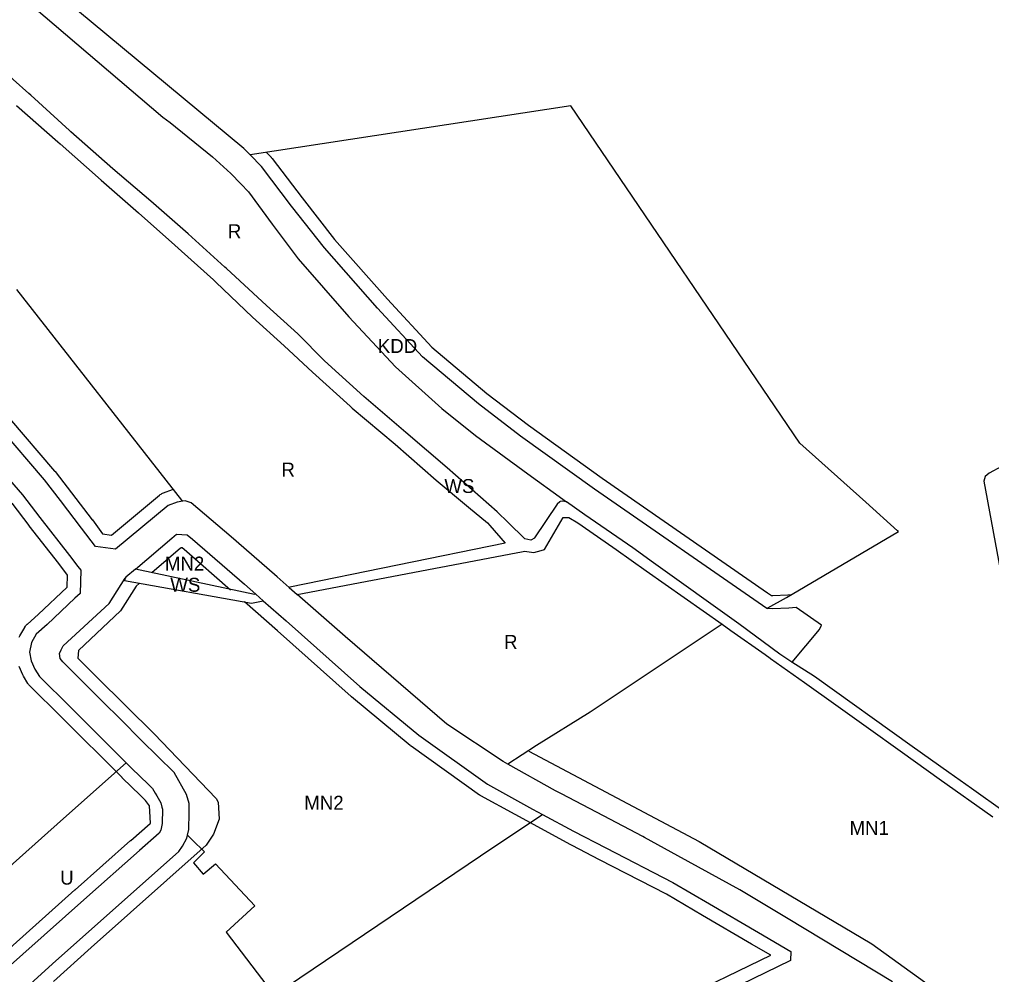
# Model space of a CAD drawing. Extents: x 7435758 to 7439981, y 5550649 to 5554049.
# Drawn here: x 7436744.6 to 7437107.4, y 5552008.2 to 5552364.7 of the extents above; entities that cross this region are included whole.
import ezdxf

# ---------------------------------------------------------------- set-up
doc = ezdxf.new("R2010")
doc.units = 0
for name, color, linetype in [('linie_rozgraniczające', 7, 'Continuous'), ('linie_zabudowy_nieprzekraczalne', 7, 'Continuous'), ('oznaczenia_przeznaczen', 7, 'Continuous')]:
    doc.layers.add(name, color=color, linetype=linetype)

msp = doc.modelspace()

# ---------------------------------------------------------------- linework, layer by layer
at = {"layer": 'linie_rozgraniczające'}
for p, q in [((7436737.83, 5552379.62), (7436798.12, 5552328.15)), ((7436828.32, 5552316.54), (7436754.67, 5552377.68)), ((7436748.06, 5552337.04), (7436734.36, 5552349.15)), ((7436748.82, 5552336.34), (7436748.06, 5552337.04)), ((7436763.28, 5552323.19), (7436748.82, 5552336.34)), ((7436743.48, 5552332.53), (7436758.9, 5552319)), ((7436950.34, 5552332.41), (7436830.7, 5552314.09)), ((7437035.85, 5552206.58), (7436950.34, 5552332.41)), ((7436798.12, 5552328.15), (7436800.78, 5552326.16)), ((7436800.78, 5552326.16), (7436816.7, 5552313.41)), ((7436763.78, 5552322.75), (7436763.28, 5552323.19)), ((7436779.47, 5552308.86), (7436763.78, 5552322.75)), ((7436758.9, 5552319), (7436759.8, 5552318.19)), ((7436759.8, 5552318.19), (7436775.04, 5552304.67)), ((7436816.7, 5552313.41), (7436823.53, 5552307.12)), ((7436830.7, 5552314.09), (7436828.32, 5552316.54)), ((7436834.92, 5552309.73), (7436830.7, 5552314.09)), ((7436846.12, 5552295.03), (7436834.92, 5552309.73)), ((7436793.58, 5552296.81), (7436779.47, 5552308.86)), ((7436823.53, 5552307.12), (7436827.24, 5552303.29)), ((7436775.04, 5552304.67), (7436789.02, 5552292.46)), ((7436827.24, 5552303.29), (7436830.12, 5552300.32)), ((7436830.12, 5552300.32), (7436838.94, 5552288.29)), ((7436802.59, 5552289.01), (7436793.58, 5552296.81)), ((7436789.02, 5552292.46), (7436802.61, 5552280.39)), ((7436858.38, 5552279.36), (7436846.12, 5552295.03)), ((7436807.58, 5552284.69), (7436802.59, 5552289.01)), ((7436838.94, 5552288.29), (7436848.57, 5552275.3)), ((7436821.22, 5552272.23), (7436807.58, 5552284.69)), ((7436802.61, 5552280.39), (7436805.12, 5552278.15)), ((7436805.12, 5552278.15), (7436816.98, 5552267.53)), ((7436878.24, 5552256.92), (7436858.38, 5552279.36)), ((7436848.57, 5552275.3), (7436867.5, 5552253.71)), ((7436821.84, 5552271.66), (7436821.22, 5552272.23)), ((7436836.85, 5552257.92), (7436821.84, 5552271.66)), ((7436816.98, 5552267.53), (7436817.87, 5552266.67)), ((7436817.87, 5552266.67), (7436831.59, 5552253.59)), ((7436805.24, 5552185.29), (7436743.6, 5552263.84)), ((7436848.47, 5552247.33), (7436836.85, 5552257.92)), ((7436895.01, 5552238.78), (7436878.24, 5552256.92)), ((7436831.59, 5552253.59), (7436843.39, 5552242.82)), ((7436867.5, 5552253.71), (7436884.94, 5552234.96)), ((7436858.46, 5552237.27), (7436848.47, 5552247.33)), ((7436843.39, 5552242.82), (7436854, 5552233.07)), ((7436873.11, 5552223.95), (7436858.46, 5552237.27)), ((7436915.94, 5552221.19), (7436895.01, 5552238.78)), ((7436884.94, 5552234.96), (7436902.24, 5552219.5)), ((7436854, 5552233.07), (7436868.01, 5552220.32)), ((7436888.83, 5552210.56), (7436873.11, 5552223.95)), ((7436868.01, 5552220.32), (7436868.82, 5552219.58)), ((7436868.82, 5552219.58), (7436884.81, 5552206.12)), ((7436902.24, 5552219.5), (7436914.77, 5552209.39)), ((7436931.58, 5552209.19), (7436915.94, 5552221.19)), ((7436753.92, 5552192.88), (7436737.06, 5552212.54)), ((7436904.23, 5552197.29), (7436888.83, 5552210.56)), ((7436914.77, 5552209.39), (7436934.3, 5552195.03)), ((7436959.17, 5552189.34), (7436931.58, 5552209.19)), ((7436884.81, 5552206.12), (7436900.09, 5552192.66)), ((7437060.43, 5552184.47), (7437035.85, 5552206.58)), ((7436922.86, 5552180.92), (7436904.23, 5552197.29)), ((7437116.22, 5552200.66), (7437106.53, 5552195.37)), ((7436739.31, 5552194.7), (7436745.79, 5552187.3)), ((7436934.3, 5552195.03), (7436947.34, 5552185.68)), ((7437104.98, 5552194.03), (7437104.48, 5552192.3)), ((7437106.53, 5552195.37), (7437104.98, 5552194.03)), ((7436759.87, 5552185.15), (7436753.92, 5552192.88)), ((7436900.09, 5552192.66), (7436912.13, 5552182.68)), ((7437104.48, 5552192.3), (7437129.36, 5552057.48)), ((7436745.79, 5552187.3), (7436752.23, 5552178.76)), ((7437023.5, 5552144.84), (7436959.17, 5552189.34)), ((7436767.8, 5552174.85), (7436759.87, 5552185.15)), ((7436800.11, 5552183.31), (7436780.41, 5552166.99)), ((7436803.46, 5552184.56), (7436800.11, 5552183.31)), ((7436805.53, 5552184.85), (7436803.46, 5552184.56)), ((7436805.53, 5552184.85), (7436805.24, 5552185.29)), ((7436806.41, 5552184.97), (7436805.53, 5552184.85)), ((7436808.74, 5552184.32), (7436806.41, 5552184.97)), ((7436823.61, 5552171.62), (7436808.74, 5552184.32)), ((7436945.22, 5552183.81), (7436936.82, 5552171.22)), ((7436946.21, 5552184.68), (7436945.22, 5552183.81)), ((7436946.34, 5552184.7), (7436946.21, 5552184.68)), ((7436947.3, 5552184.9), (7436946.34, 5552184.7)), ((7436948.75, 5552184.67), (7436947.3, 5552184.9)), ((7436947.34, 5552185.68), (7436948.75, 5552184.67)), ((7436955.64, 5552179.73), (7436948.75, 5552184.67)), ((7437072.34, 5552173.76), (7437060.43, 5552184.47)), ((7436912.13, 5552182.68), (7436919.25, 5552176.78)), ((7436926.96, 5552176.9), (7436922.86, 5552180.92)), ((7436973.49, 5552167.41), (7436955.64, 5552179.73)), ((7436752.23, 5552178.76), (7436763.23, 5552164.63)), ((7436919.25, 5552176.78), (7436920.17, 5552175.74)), ((7436920.17, 5552175.74), (7436925.93, 5552169.25)), ((7436933.16, 5552170.85), (7436926.96, 5552176.9)), ((7436940.55, 5552166.89), (7436947.54, 5552178.8)), ((7436947.54, 5552178.8), (7436948.54, 5552178.78)), ((7436948.54, 5552178.78), (7436949.63, 5552178.77)), ((7436949.63, 5552178.77), (7436949.66, 5552178.77)), ((7436949.66, 5552178.77), (7436952.97, 5552176.78)), ((7436952.97, 5552176.78), (7436963.22, 5552169.7)), ((7436773.01, 5552167.95), (7436767.8, 5552174.85)), ((7436801.5, 5552171.12), (7436803.17, 5552172.56)), ((7436803.17, 5552172.56), (7436807.16, 5552172.31)), ((7436807.16, 5552172.31), (7436809.23, 5552170.75)), ((7437030.91, 5552148.93), (7437072.61, 5552173.52)), ((7437072.61, 5552173.52), (7437072.34, 5552173.76)), ((7436787.94, 5552159.56), (7436801.5, 5552171.12)), ((7436809.23, 5552170.75), (7436828.55, 5552153.85)), ((7436834.07, 5552162.48), (7436823.61, 5552171.62)), ((7436925.93, 5552169.25), (7436845.47, 5552152.77)), ((7436935.42, 5552170.37), (7436933.16, 5552170.85)), ((7436936.76, 5552171.13), (7436935.42, 5552170.37)), ((7436936.82, 5552171.22), (7436936.76, 5552171.13)), ((7436963.22, 5552169.7), (7436967.29, 5552166.81)), ((7436763.23, 5552164.63), (7436766.33, 5552160.44)), ((7436780.41, 5552166.99), (7436773.01, 5552167.95)), ((7436848.24, 5552150.08), (7436930.03, 5552165.6)), ((7436930.03, 5552165.6), (7436931.98, 5552165.97)), ((7436931.98, 5552165.97), (7436933.27, 5552166.22)), ((7436933.27, 5552166.22), (7436933.92, 5552166.12)), ((7436933.92, 5552166.12), (7436936.58, 5552165.71)), ((7436936.58, 5552165.71), (7436939.33, 5552166.53)), ((7436939.33, 5552166.53), (7436940.55, 5552166.89)), ((7436967.29, 5552166.81), (7436978.5, 5552158.85)), ((7436981.26, 5552161.81), (7436973.49, 5552167.41)), ((7436840.77, 5552156.63), (7436834.07, 5552162.48)), ((7437013.02, 5552139.1), (7436981.26, 5552161.81)), ((7436766.33, 5552160.44), (7436767.54, 5552159.15)), ((7436767.54, 5552159.15), (7436767.27, 5552150.48)), ((7436787.94, 5552159.56), (7436784.31, 5552156.47)), ((7436822.42, 5552152.11), (7436787.94, 5552159.56)), ((7436978.5, 5552158.85), (7437006.81, 5552138.93)), ((7436778.08, 5552146.7), (7436784.08, 5552156.11)), ((7436784.08, 5552156.11), (7436783.84, 5552155.27)), ((7436783.84, 5552155.27), (7436831.22, 5552146.85)), ((7436784.31, 5552156.47), (7436784.08, 5552156.11)), ((7436828.55, 5552153.85), (7436832.81, 5552150.13)), ((7436845.23, 5552152.72), (7436840.77, 5552156.63)), ((7436767.27, 5552150.48), (7436765.31, 5552148.66)), ((7436832.37, 5552150.04), (7436822.42, 5552152.11)), ((7436832.81, 5552150.13), (7436832.37, 5552150.04)), ((7436835.61, 5552147.69), (7436832.81, 5552150.13)), ((7436845.47, 5552152.77), (7436845.23, 5552152.72)), ((7436845.23, 5552152.72), (7436848.24, 5552150.08)), ((7436866.1, 5552134.44), (7436848.24, 5552150.08)), ((7436765.31, 5552148.66), (7436754.95, 5552138.9)), ((7436760.97, 5552130.85), (7436778.08, 5552146.7)), ((7436831.22, 5552146.85), (7436835.61, 5552147.69)), ((7436835.61, 5552147.69), (7436844.15, 5552140.22)), ((7437023.91, 5552145.07), (7437030.86, 5552148.9)), ((7437030.86, 5552148.9), (7437030.91, 5552148.93)), ((7437023.5, 5552144.84), (7437023.91, 5552145.07)), ((7437023.92, 5552144.8), (7437023.5, 5552144.84)), ((7437025.59, 5552144.65), (7437023.92, 5552144.8)), ((7437031.78, 5552144.9), (7437025.59, 5552144.65)), ((7437034.43, 5552145.22), (7437031.78, 5552144.9)), ((7437043.91, 5552138.61), (7437034.43, 5552145.22)), ((7436844.15, 5552140.22), (7436871.67, 5552115.67)), ((7436754.95, 5552138.9), (7436750.88, 5552135.3)), ((7437006.81, 5552138.93), (7436957.6, 5552106.19)), ((7437006.81, 5552138.93), (7437010.06, 5552136.65)), ((7437010.06, 5552136.65), (7437022.88, 5552127.61)), ((7437028.36, 5552127.76), (7437013.02, 5552139.1)), ((7437032.92, 5552124.86), (7437043.12, 5552137.04)), ((7437043.12, 5552137.04), (7437043.91, 5552138.61)), ((7436749.07, 5552132.12), (7436748.31, 5552128.59)), ((7436750.88, 5552135.3), (7436749.07, 5552132.12)), ((7436904.15, 5552101.63), (7436866.1, 5552134.44)), ((7436748.31, 5552128.59), (7436748.96, 5552125.25)), ((7436759.53, 5552128.07), (7436760.13, 5552129.39)), ((7436760.13, 5552129.39), (7436760.97, 5552130.85)), ((7436748.96, 5552125.25), (7436750.38, 5552122.19)), ((7436759.74, 5552126.14), (7436759.53, 5552128.07)), ((7436760.83, 5552124.89), (7436759.74, 5552126.14)), ((7436775.75, 5552110.01), (7436760.83, 5552124.89)), ((7437022.88, 5552127.61), (7437024.81, 5552126.26)), ((7437024.81, 5552126.26), (7437024.86, 5552126.22)), ((7437024.86, 5552126.22), (7437037.54, 5552117.2)), ((7437032.91, 5552124.85), (7437028.36, 5552127.76)), ((7437032.91, 5552124.85), (7437032.92, 5552124.86)), ((7437041.31, 5552119.46), (7437032.91, 5552124.85)), ((7436750.38, 5552122.19), (7436752.05, 5552119.41)), ((7436752.05, 5552119.41), (7436763.65, 5552107.96)), ((7437077.79, 5552093.32), (7437041.31, 5552119.46)), ((7436871.67, 5552115.67), (7436893.64, 5552097.51)), ((7437037.54, 5552117.2), (7437037.56, 5552117.18)), ((7437037.56, 5552117.18), (7437049.24, 5552108.86)), ((7436763.65, 5552107.96), (7436774.86, 5552096.77)), ((7436782.28, 5552103.48), (7436775.75, 5552110.01)), ((7437049.24, 5552108.86), (7437060.58, 5552100.78)), ((7436790.2, 5552095.57), (7436782.28, 5552103.48)), ((7436957.6, 5552106.19), (7436937.56, 5552093.73)), ((7436925.11, 5552087.7), (7436904.15, 5552101.63)), ((7437060.58, 5552100.78), (7437074.16, 5552091.09)), ((7436774.86, 5552096.77), (7436784.37, 5552087.28)), ((7436893.64, 5552097.51), (7436919.24, 5552079.31)), ((7436802.37, 5552083.59), (7436790.2, 5552095.57)), ((7436937.56, 5552093.73), (7436926.91, 5552086.7)), ((7437091.42, 5552083.6), (7437077.79, 5552093.32)), ((7437074.16, 5552091.09), (7437087.82, 5552081.28)), ((7436761.03, 5552066.45), (7436784.37, 5552087.28)), ((7436784.37, 5552087.28), (7436786.4, 5552085.24)), ((7436786.4, 5552085.24), (7436792.76, 5552079.14)), ((7436926.91, 5552086.7), (7436925.11, 5552087.7)), ((7436944.67, 5552076.81), (7436926.91, 5552086.7)), ((7436806.91, 5552075.42), (7436802.37, 5552083.59)), ((7437087.82, 5552081.28), (7437107.84, 5552067.1)), ((7437099.88, 5552077.62), (7437091.42, 5552083.6)), ((7436792.76, 5552079.14), (7436794.29, 5552077.67)), ((7436794.29, 5552077.67), (7436794.8, 5552076.77)), ((7436919.24, 5552079.31), (7436936.11, 5552069.99)), ((7437112.44, 5552068.75), (7437099.88, 5552077.62)), ((7436794.8, 5552076.77), (7436795.27, 5552075.92)), ((7436795.27, 5552075.92), (7436795.86, 5552074.86)), ((7436795.86, 5552074.86), (7436797.31, 5552072.31)), ((7436807.88, 5552072.02), (7436806.91, 5552075.42)), ((7436946.88, 5552075.65), (7436944.67, 5552076.81)), ((7436962.51, 5552067.44), (7436946.88, 5552075.65)), ((7436797.31, 5552072.31), (7436797.78, 5552070.66)), ((7436797.78, 5552070.66), (7436797.97, 5552069.97)), ((7436807.98, 5552068.59), (7436807.88, 5552072.02)), ((7436797.97, 5552069.97), (7436797.81, 5552064.61)), ((7436807.76, 5552062.36), (7436807.98, 5552068.59)), ((7436921.59, 5552055.85), (7436939.82, 5552067.99)), ((7436936.11, 5552069.99), (7436939.82, 5552067.99)), ((7436939.82, 5552067.99), (7436951.41, 5552061.74)), ((7436977.21, 5552059.72), (7436962.51, 5552067.44)), ((7436716.64, 5552026.84), (7436761.03, 5552066.45)), ((7436797.81, 5552064.61), (7436797.37, 5552062.16)), ((7436796.78, 5552060.93), (7436789.4, 5552054.47)), ((7436797.37, 5552062.16), (7436796.78, 5552060.93)), ((7436807.03, 5552059.11), (7436807.27, 5552060.18)), ((7436807.27, 5552060.18), (7436807.76, 5552062.36)), ((7436807.27, 5552060.18), (7436809.01, 5552058.5)), ((7436951.41, 5552061.74), (7436963.4, 5552055.53)), ((7436977.86, 5552059.36), (7436977.21, 5552059.72)), ((7436990.35, 5552052.51), (7436977.86, 5552059.36)), ((7436804.1, 5552054.14), (7436805.46, 5552056.09)), ((7436805.46, 5552056.09), (7436807.03, 5552059.11)), ((7436809.01, 5552058.5), (7436813.62, 5552054.07)), ((7436839.63, 5552000.51), (7436921.59, 5552055.85)), ((7436756.98, 5552012.28), (7436804.1, 5552054.14)), ((7436789.4, 5552054.47), (7436768.64, 5552036.13)), ((7436813.62, 5552054.07), (7436809.59, 5552049.96)), ((7436963.4, 5552055.53), (7436988.45, 5552042.61)), ((7437013.47, 5552039.85), (7436990.35, 5552052.51)), ((7436809.59, 5552049.96), (7436813.22, 5552045.67)), ((7436813.22, 5552045.67), (7436817.74, 5552049.55)), ((7436817.74, 5552049.55), (7436832.43, 5552033.88)), ((7436988.45, 5552042.61), (7437002.07, 5552034.61)), ((7437031.54, 5552029.05), (7437013.47, 5552039.85)), ((7436768.64, 5552036.13), (7436739.01, 5552009.68)), ((7437002.07, 5552034.61), (7437020.36, 5552023.94)), ((7436832.43, 5552033.88), (7436821.74, 5552024.08)), ((7437070.47, 5552005.57), (7437031.54, 5552029.05)), ((7436821.74, 5552024.08), (7436838.9, 5552001.48)), ((7437020.36, 5552023.94), (7437032.48, 5552016.87)), ((7437032.48, 5552016.87), (7437032.35, 5552013.43)), ((7436745.81, 5552002.16), (7436756.98, 5552012.28)), ((7437032.35, 5552013.43), (7436990.74, 5551993.3))]:
    msp.add_line(p, q, dxfattribs=at)
at = {"layer": 'linie_zabudowy_nieprzekraczalne'}
for points in [[(7436836.75, 5552315.03), (7436838.51, 5552313.21), (7436838.54, 5552313.18), (7436838.76, 5552312.93), (7436838.89, 5552312.76), (7436850.08, 5552298.08), (7436862.22, 5552282.56), (7436881.94, 5552260.28), (7436898.47, 5552242.41), (7436919.07, 5552225.09), (7436934.57, 5552213.21), (7436962.05, 5552193.43), (7437023.79, 5552150.71), (7437025.25, 5552149.7), (7437025.71, 5552149.66), (7437031.38, 5552149.89), (7437032.75, 5552150.06)], [(7436661.08, 5552307.31), (7436661.24, 5552307.14), (7436684.11, 5552280.48), (7436706.93, 5552254.42), (7436740.82, 5552215.83), (7436740.86, 5552215.79), (7436757.72, 5552196.14), (7436757.76, 5552196.08), (7436757.88, 5552195.93), (7436771.77, 5552177.9), (7436771.8, 5552177.86), (7436775.61, 5552172.65), (7436778.9, 5552172.22), (7436796.92, 5552187.16), (7436797.17, 5552187.35), (7436797.44, 5552187.54), (7436797.72, 5552187.7), (7436798.01, 5552187.85), (7436798.31, 5552187.98), (7436798.37, 5552188), (7436801.72, 5552189.24), (7436801.98, 5552189.33), (7436802.01, 5552189.34)], [(7436744.5, 5552134.14), (7436744.64, 5552134.44), (7436744.73, 5552134.59), (7436746.54, 5552137.78), (7436746.62, 5552137.91), (7436746.8, 5552138.18), (7436746.99, 5552138.44), (7436747.21, 5552138.69), (7436747.44, 5552138.92), (7436747.57, 5552139.04), (7436751.58, 5552142.59), (7436762.34, 5552152.73), (7436762.48, 5552157.25), (7436759.25, 5552161.6), (7436748.28, 5552175.68), (7436748.24, 5552175.75), (7436741.91, 5552184.15)], [(7436823.4, 5552151.73), (7436806.07, 5552166.86), (7436805.35, 5552167.41), (7436804.89, 5552167.44), (7436804.77, 5552167.34), (7436804.75, 5552167.31), (7436794.03, 5552158.09)], [(7436789.3, 5552154.17), (7436788.15, 5552153.19), (7436782.3, 5552144.01), (7436766.67, 5552129.2), (7436766.39, 5552126.3), (7436773.23, 5552119.5), (7436784.38, 5552108.4), (7436794.83, 5552098.03), (7436818.07, 5552073.98), (7436818.76, 5552072.52), (7436819.15, 5552066.18), (7436816.99, 5552060.66), (7436814.25, 5552056.45), (7436771.3, 5552018.3), (7436757.24, 5552005.64)], [(7436988.58, 5551997.81), (7437025.03, 5552015.44), (7437017.84, 5552019.62), (7436999.55, 5552030.29), (7436999.54, 5552030.3), (7436986.03, 5552038.23), (7436961.11, 5552051.09), (7436961.1, 5552051.09), (7436950.87, 5552056.39), (7436950.4, 5552056.64), (7436929.64, 5552067.95), (7436916.83, 5552074.93), (7436916.64, 5552075.04), (7436916.36, 5552075.22), (7436916.35, 5552075.23), (7436890.75, 5552093.43), (7436890.5, 5552093.62), (7436890.46, 5552093.65), (7436868.48, 5552111.81), (7436868.34, 5552111.94), (7436840.84, 5552136.47), (7436828.53, 5552147.33)], [(7436737.28, 5552014.85), (7436765.31, 5552039.86), (7436765.33, 5552039.88), (7436786.09, 5552058.21), (7436786.11, 5552058.23), (7436793.42, 5552064.62), (7436793.5, 5552064.7), (7436793.24, 5552069.11), (7436793.16, 5552071.21), (7436791.68, 5552073.24), (7436789.82, 5552075.03), (7436782.94, 5552081.64), (7436782.87, 5552081.71), (7436760.13, 5552104.42), (7436748.54, 5552115.85), (7436748.42, 5552115.97), (7436748.21, 5552116.21), (7436748.01, 5552116.47), (7436747.82, 5552116.74), (7436747.76, 5552116.84), (7436746.09, 5552119.62), (7436745.99, 5552119.8), (7436745.85, 5552120.09), (7436744.43, 5552123.14)], [(7436934.74, 5552091.63), (7436998.26, 5552057.84), (7437062.75, 5552019.65), (7437099.78, 5551992.9), (7437113.79, 5551981.52)]]:
    msp.add_lwpolyline(points, dxfattribs=at)

# ---------------------------------------------------------------- texts
at = {"layer": 'oznaczenia_przeznaczen'}
for s, p in [('R', (7436822.36, 5552283.02)), ('KDD', (7436878.35, 5552240.18)), ('R', (7436842.37, 5552194.07)), ('WS', (7436903.19, 5552187.94)), ('MN2', (7436798.88, 5552158.98)), ('WS', (7436800.9, 5552151.08)), ('R', (7436925.45, 5552129.77)), ('MN2', (7436850.9, 5552069.74)), ('MN1', (7437054.4, 5552060.34)), ('U', (7436759.8, 5552041.78))]:
    msp.add_text(s, height=5.2, dxfattribs=at).set_placement(p)

doc.saveas('drawing.dxf')
